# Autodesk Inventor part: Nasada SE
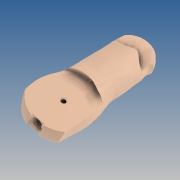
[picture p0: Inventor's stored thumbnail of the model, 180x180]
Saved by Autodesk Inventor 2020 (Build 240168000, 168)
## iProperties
Created: 2019-10
Part Number: Nasada SE
Material: GFRP
Document SubType Name: Modeling
Designer: yello
Density: 1.75 g/cm^3
Appearance: Default
Author: yello
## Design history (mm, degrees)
node "Annotations"
  node "Leader Text 1"
feature "Nasada SE"
workplane "Work Plane1"
sketch "Sketch1"
  geometry: L1 (3.426, -0.717)-(7.524, 18.858); L2 (7.524, 18.858)-(0.672, 20.293); L3 (0.672, 20.293)-(-3.426, 0.717); L4 (-3.426, 0.717)-(-9.573, -28.646); L5 (-9.573, -28.646)-(-2.722, -30.081); L6 (-2.722, -30.081)-(3.426, -0.717); L7 (-6.147, -29.363)-(4.098, 19.576); A1 r 3.5 centre (0, 0) between (3.426, -0.717) and (-3.426, 0.717)
  constraints: 14 end point, 3 perpendicular, 2 midpoint, 2 point on circle, 2 point on line, 2 tangent, 1 centre point
  dimensions: "d0" = 7 diameter of A1; "d1" = 20 distance of L1.start L1.end; "d2" = 30 distance of L3.end L4.end
revolve "Revolution1" sketch "Sketch1" stored, may be unused: angle "d3" = 90 deg
workplane "Work Plane2"
workplane "Work Plane3"
workplane "Work Plane4"
sketch "Sketch2" dims "d8" = 3
  geometry: L1 (-2.722, -30.081)-(-9.573, -28.646); L2 (-6.147, -29.363)-(0, 0); L3 (0, 0)-(0.307, 1.468); 2 further points
  constraints: 6 end point, 1 coincident, 1 midpoint, 3 other
  dimensions: "d7" = 30 distance of L2.start L2.end
revolve "Revolution2" sketch "Sketch2" stored, may be unused: angle "d9" = 90 deg
mirror "Mirror1"
workplane "Work Plane5"
sketch "Sketch6"
  geometry: L1 (-0.147, 13.857)-(-0.093, 6.857) reference; L2 (-0.12, 10.357)-(3.63, 10.386); L3 (3.63, 10.386)-(11.879, 10.449); L4 (3.637, 9.386)-(11.887, 9.449); L5 (11.872, 11.449)-(3.622, 11.386); A1 r 1 centre (3.63, 10.386) between (3.622, 11.386) and (3.637, 9.386); A2 r 1 centre (11.879, 10.449) between (11.887, 9.449) and (11.872, 11.449); 2 further points
  constraints: 10 end point, 4 point on circle, 4 tangent, 2 centre point, 2 midpoint, 2 parallel, 1 perpendicular
  dimensions: "d22" = 3.75 distance of L2.start L2.end; "d23" = 8.25 distance of L2.end L3.end; "d24" = 2 diameter of A2
extrude "Extrusion3" cut sketch "Sketch6" distance "d25" = 14; taper "d26" = 0 deg
workplane "Work Plane6"
sketch "Sketch7"
  geometry: C1 r 4.25 at (0, 0)
  constraints: 1 centre point
  dimensions: "d28" = 8.5 diameter of C1
extrude "Extrusion4" cut sketch "Sketch7" distance "d29" = 1.75; taper "d30" = 0 deg
fillet "Fillet1" dims "d31" = 1
body "Solid1"
other parameters: "d4" = 0, "d6" = -0.5, "d27" = 48, "d15" = 7.42011 (derived), "d16" = 6.081 (derived)
